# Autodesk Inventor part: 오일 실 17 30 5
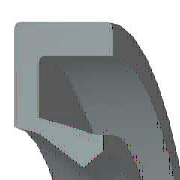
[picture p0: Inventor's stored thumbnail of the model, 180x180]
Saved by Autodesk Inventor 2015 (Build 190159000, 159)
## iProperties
IsCustomPart: 1
Created: 2012-02
Part Number: 오일 실 17 30 5
Material: 고무
Description: 오일 실 - 비스프링, 조립 GA
Document SubType Name: Modeling
Standard: JIS B 2402
Designer: mduedu
Standards Organization: JIS
Language: ko-KR
Size Designation: 17 30 5 A
Categories: <MemberInstance><Categories><Category DisplayName="샤프트 부품" InternalName="7f7aeb1f-a693-4053-b835-cee3144e0d98" Mnemonic="SHFT"><Category DisplayName="실링" Intern
Density: 0.93 g/cm^3
Appearance: Rubber-Black
Mass: 1.39335 g
Surface Area: 19.422 cm^2
Volume: 1.49822 cm^3
Author: mduedu
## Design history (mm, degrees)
body "Solid1"
revolve "회전1" stored, may be unused: angle "d27" = 360 deg
fillet "모깎기1" dims "d28" = 0.25 (= 0.05 x b)
sketch "스케치2"
  geometry: L1 (10.636, -3.75)-(11.286, -5); L2 (9.769, -3.438)-(10.636, -3.75); L3 (8.5, -1.375)-(9.769, -3.438); L4 (9.5, -0.75)-(8.5, -1.375); L5 (12.4, -4.375)-(9.5, -0.75); L6 (12.4, -0.25)-(12.4, -4.375); L7 (13.7, -0.25)-(12.4, -0.25); L8 (13.7, 0)-(13.7, -0.25); L9 (15, 0)-(13.7, 0); L10 (15, -5)-(15, 0); L11 (11.286, -5)-(15, -5); L12 (0, -9.6)-(0, 1.6) reference; L13 (28, 0)-(14, 0) reference
  constraints: 22 end point, 3 horizontal, 3 vertical
  dimensions: "d2" = 5 distance of L10.start L9.start (= b); "d4" = 1.3 distance of L9.start L8.start (= 0.1 x dd - 0.1 x Diam); "d6" = 0.25 distance of L8.start L7.start (= 0.05 x b); "d8" = 1 horizontal distance of L4.start L3.start (= 0.0769231 x dd - 0.0769231 x Diam); "d10" = 0.625 vertical distance of L5.start L10.start (= 0.125 x b); "d12" = 1.3 distance of L7.start L6.start (= 0.1 x dd - 0.1 x Diam); "d14" = 0.5 vertical distance of L4.start L6.start (= 0.1 x b); "d16" = 3.71429 distance of L1.end L10.start (= 0.285714 x dd - 0.285714 x Diam); "d18" = 0.65 horizontal distance of L1.start L1.end (= 0.05 x dd - 0.05 x Diam); "d20" = 0.625 vertical distance of L4.start L3.start (= 0.125 x b); "d22" = 1.25 vertical distance of L1.start L1.end (= 0.25 x b); "d24" = 0.86667 horizontal distance of L2.start L1.start (= 0.0666667 x dd - 0.0666667 x Diam); "d26" = 0.3125 vertical distance of L2.start L1.start (= 0.0625 x b); "d29" = 0 distance between parallel lines of L13 L9; "d30" = 8.5 distance from line of L3.start L12 (= 0.5 x Diam); "d31" = 15 distance between parallel lines of L12 L10 (= 0.5 x dd)
other parameters: "Diam" = 17 [user parameter; used in 7 equation terms], "b" = 5 [user parameter; used in 8 equation terms], "d1" = 8 (derived), "d3" = 2 (derived), "d5" = 0.4 (derived), "d7" = 1.53846 (derived), "d9" = 1 (derived), "d11" = 2 (derived), "d13" = 0.8 (derived), "d15" = 5.71429 (derived), "d17" = 1 (derived), "d19" = 1 (derived), "d21" = 2 (derived), "d23" = 1.33333 (derived), "d25" = 0.5 (derived), "d32" = 0
